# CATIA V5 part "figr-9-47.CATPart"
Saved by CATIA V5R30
Part number: Part1
Bounding box of the stored display mesh (mm): x -229.955 to 192.37, y -118.044 to 79.893, z 0 to 72.429
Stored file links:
  D:\PROJECTS\CATIA V56R 2020\Resources\Parts File\c09_catia_v5_6r2020_prt\figr-9-47.CATPart
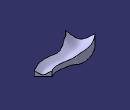
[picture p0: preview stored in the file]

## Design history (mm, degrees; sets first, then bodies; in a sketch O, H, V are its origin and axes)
Body1 (main body)
  Plane1: type Offset, RefPlane yz-plane, Offset 100
  Plane2: type Offset, RefPlane yz-plane, Offset 100, reversed
  Sketch1 on Plane1, origin (100, 0, 0), H (0, 1, 0), V (0, 0, 1)
    point P1 (0, 15.965)
    hyperbola C1
    point P2 (0, 3.0416)
    line L1 (54.8261, 44.8858) -> (54.8261, 0)
    point P5 (54.8261, 0)
    line L2 (-54.8261, 44.8858) -> (-54.8261, 0)
    point P6 (-54.8261, 0)
    line L3 (-54.8261, 0) -> (54.8261, 0)
    coincidence: P1 V, P2 V, P5 H, P6 H
    vertical: L1 V, L2 V
    horizontal: L3 H
  Sketch2 on xy-plane, origin (0, 0, 0), H (1, 0, 0), V (0, 1, 0)
    spline S1 through (-159.6608, -77.1468) (-77.8466, -31.8169) (23.6283, -41.4968) (182.6271, -11.7333)
  Sketch3 on yz-plane, origin (0, 0, 0), H (0, 1, 0), V (0, 0, 1)
    point P1 (0, 18.9787)
    hyperbola C1
    point P2 (0, 2.6681)
    line L1 (48.2237, 37.1764) -> (48.2237, 0)
    point P5 (48.2237, 0)
    line L2 (-43.6563, 34.1546) -> (-43.6563, 0)
    point P6 (-43.6563, 0)
    line L3 (-43.6563, 0) -> (48.2237, 0)
    coincidence: P1 V, P2 V, P5 H, P6 H
    vertical: L1 V, L2 V
    horizontal: L3 H
  Sketch4 on Plane2, origin (-100, 0, 0), H (0, 1, 0), V (0, 0, 1)
    point P1 (0, 140.6052)
    point P2 (0, 41.8972)
    hyperbola C1
    line L1 (78.0478, 72.4293) -> (78.0478, 0)
    point P5 (78.0478, 0)
    line L2 (-78.0478, 72.4293) -> (-78.0478, 0)
    point P6 (-78.0478, 0)
    line L3 (-78.0478, 0) -> (78.0478, 0)
    coincidence: P1 V, P2 V, P5 H, P6 H
    vertical: L1 V, L2 V
    horizontal: L3 H
  Loft1: solid, Sections (Sketch3; Sketch4), Spine Sketch2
